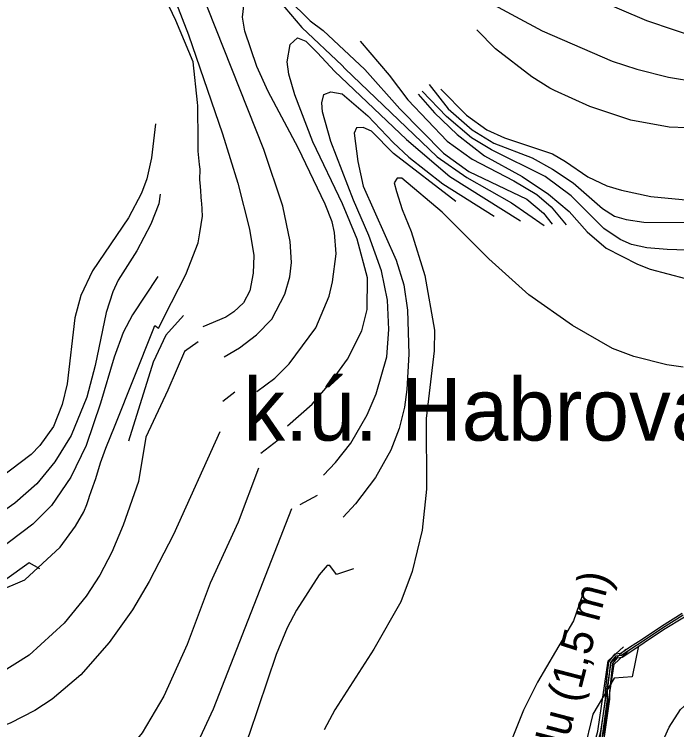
# Model space of a CAD drawing. Extents: x -1900516 to -575031, y -3809306 to -1157387.
# Drawn here: x -578473.4 to -578155.6, y -1158748.8 to -1158405.7 of the extents above; entities that cross this region are included whole.
import ezdxf

# ---------------------------------------------------------------- set-up
doc = ezdxf.new("R2010")
doc.units = 0
for name, color, linetype in [('01_SPRÁV_HRANICE', 7, 'Continuous'), ('01_VRSTEVNICE', 7, 'Continuous'), ('07_OCH_P A POPISY TI', 7, 'Continuous'), ('07_PLYNOVOD', 7, 'Continuous'), ('07_VODOVOD', 7, 'Continuous')]:
    doc.layers.add(name, color=color, linetype=linetype)

msp = doc.modelspace()

# ---------------------------------------------------------------- linework, layer by layer
at = {"layer": '01_SPRÁV_HRANICE'}
for p, q in [((-578395.81, -1158408.74), (-578400.47, -1158398.74)), ((-578395.81, -1158408.74), (-578400.47, -1158398.74)), ((-578387.52, -1158428.46), (-578395.81, -1158408.74)), ((-578387.52, -1158428.46), (-578395.81, -1158408.74)), ((-578385.48, -1158448), (-578387.52, -1158428.46)), ((-578385.48, -1158448), (-578387.52, -1158428.46)), ((-578385.3, -1158449.67), (-578385.48, -1158448)), ((-578385.3, -1158449.67), (-578385.48, -1158448)), ((-578385.27, -1158452.79), (-578385.3, -1158449.67)), ((-578385.27, -1158452.79), (-578385.3, -1158449.67)), ((-578385.17, -1158463.41), (-578385.27, -1158452.79)), ((-578385.17, -1158463.41), (-578385.27, -1158452.79)), ((-578385.09, -1158471.35), (-578385.17, -1158463.41)), ((-578385.09, -1158471.35), (-578385.17, -1158463.41)), ((-578384.48, -1158477.76), (-578385.09, -1158471.35)), ((-578384.48, -1158477.76), (-578385.09, -1158471.35)), ((-578384.27, -1158479.95), (-578384.48, -1158477.76)), ((-578384.27, -1158479.95), (-578384.48, -1158477.76)), ((-578384.3, -1158485.1), (-578384.27, -1158479.95)), ((-578384.3, -1158485.1), (-578384.27, -1158479.95)), ((-578384.08, -1158488.12), (-578384.3, -1158485.1)), ((-578384.08, -1158488.12), (-578384.3, -1158485.1)), ((-578383.52, -1158495.54), (-578384.08, -1158488.12)), ((-578383.52, -1158495.54), (-578384.08, -1158488.12)), ((-578383.48, -1158496.11), (-578383.52, -1158495.54)), ((-578383.48, -1158496.11), (-578383.52, -1158495.54)), ((-578383.11, -1158502.52), (-578383.48, -1158496.11)), ((-578383.11, -1158502.52), (-578383.48, -1158496.11)), ((-578384.39, -1158510.5), (-578383.11, -1158502.52)), ((-578384.39, -1158510.5), (-578383.11, -1158502.52)), ((-578385.18, -1158515.41), (-578384.39, -1158510.5)), ((-578385.18, -1158515.41), (-578384.39, -1158510.5)), ((-578391.1, -1158530.59), (-578385.18, -1158515.41)), ((-578391.1, -1158530.59), (-578385.18, -1158515.41)), ((-578397.98, -1158544.02), (-578391.1, -1158530.59)), ((-578397.98, -1158544.02), (-578391.1, -1158530.59)), ((-578404.22, -1158556.2), (-578397.98, -1158544.02)), ((-578404.22, -1158556.2), (-578397.98, -1158544.02)), ((-578406.73, -1158557.02), (-578405.95, -1158555.06)), ((-578406.73, -1158557.02), (-578405.95, -1158555.06)), ((-578405.95, -1158555.06), (-578404.22, -1158556.2)), ((-578405.95, -1158555.06), (-578404.22, -1158556.2)), ((-578424.95, -1158602.79), (-578406.73, -1158557.02)), ((-578424.95, -1158602.79), (-578406.73, -1158557.02)), ((-578429.47, -1158613.84), (-578424.95, -1158602.79)), ((-578429.47, -1158613.84), (-578424.95, -1158602.79)), ((-578432, -1158620.85), (-578429.47, -1158613.84)), ((-578432, -1158620.85), (-578429.47, -1158613.84)), ((-578434.23, -1158628.36), (-578432, -1158620.85)), ((-578434.23, -1158628.36), (-578432, -1158620.85)), ((-578436.33, -1158634.06), (-578434.23, -1158628.36)), ((-578436.33, -1158634.06), (-578434.23, -1158628.36)), ((-578437.44, -1158637.36), (-578436.33, -1158634.06)), ((-578437.44, -1158637.36), (-578436.33, -1158634.06)), ((-578438.63, -1158640.88), (-578437.48, -1158637.49)), ((-578438.63, -1158640.88), (-578437.48, -1158637.49)), ((-578437.48, -1158637.49), (-578437.44, -1158637.36)), ((-578437.48, -1158637.49), (-578437.44, -1158637.36)), ((-578439.98, -1158644.37), (-578438.63, -1158640.88)), ((-578439.98, -1158644.37), (-578438.63, -1158640.88)), ((-578444.04, -1158651.25), (-578439.98, -1158644.37)), ((-578444.04, -1158651.25), (-578439.98, -1158644.37)), ((-578451.4, -1158661.35), (-578444.04, -1158651.25)), ((-578451.4, -1158661.35), (-578444.04, -1158651.25)), ((-578468.26, -1158676.95), (-578451.4, -1158661.35)), ((-578468.26, -1158676.95), (-578451.4, -1158661.35)), ((-578482.31, -1158682.92), (-578468.26, -1158676.95)), ((-578482.31, -1158682.92), (-578468.26, -1158676.95))]:
    msp.add_line(p, q, dxfattribs=at)
at = {"layer": '01_VRSTEVNICE'}
for points in [[(-578348.74, -1158381.16), (-578359.04, -1158370.16), (-578383.03, -1158347.72), (-578410.12, -1158320.77), (-578418.02, -1158314.57), (-578423.95, -1158311.32), (-578426.2, -1158310.9), (-578430.15, -1158312.87), (-578430.58, -1158313.72), (-578429.73, -1158319.65), (-578423.24, -1158336.58), (-578413.93, -1158357.74), (-578407.16, -1158370.44), (-578389.8, -1158415.59), (-578373.44, -1158463), (-578366.1, -1158486.7), (-578360.6, -1158508.71), (-578358.48, -1158521.41), (-578358.76, -1158529.87), (-578360.45, -1158538.34), (-578363.42, -1158544.12), (-578368.07, -1158548.5), (-578371.88, -1158551.04), (-578382.89, -1158555.55)], [(-578039.61, -1158382.57), (-578046.81, -1158422.36), (-578051.04, -1158436.19), (-578056.96, -1158445.36), (-578060.63, -1158449.03), (-578065.29, -1158451.99), (-578072.06, -1158454.25), (-578080.53, -1158455.66), (-578108.46, -1158455.66), (-578123.98, -1158458.34), (-578142.33, -1158460.46), (-578159.26, -1158459.89), (-578177.6, -1158456.51), (-578197.35, -1158450.02), (-578214.28, -1158442.26), (-578216.54, -1158441.13), (-578225.15, -1158435.77), (-578242.5, -1158422.22), (-578251.53, -1158413.19)], [(-578372.73, -1158569.94), (-578365.39, -1158565.71), (-578357.21, -1158559.5), (-578349.87, -1158551.88), (-578343.66, -1158540.03), (-578341.12, -1158531.57), (-578340.42, -1158524.79), (-578340.98, -1158514.64), (-578344.51, -1158497.71), (-578353.68, -1158470.61), (-578384.44, -1158393.01)], [(-578073.33, -1158400.92), (-578083.63, -1158411.36), (-578090.4, -1158415.59), (-578096.05, -1158417.85), (-578108.46, -1158420.1), (-578125.39, -1158419.96), (-578143.45, -1158417.85), (-578169.91, -1158408.8), (-578208.18, -1158392.36)], [(-578342.25, -1158397.95), (-578331.39, -1158408.82), (-578325.18, -1158413.47), (-578305.15, -1158432.24), (-578288.5, -1158451.14), (-578267.47, -1158472.31), (-578255.34, -1158481.06), (-578227.55, -1158494.32), (-578219.5, -1158501.09), (-578215.41, -1158506.45)], [(-578357.07, -1158586.59), (-578348.32, -1158580.24), (-578341.55, -1158573.33), (-578328.71, -1158556.12), (-578322.36, -1158540.88), (-578320.67, -1158534.11), (-578318.97, -1158520.56), (-578319.82, -1158510.4), (-578320.95, -1158505.32), (-578324.19, -1158496.86), (-578337.17, -1158469.77), (-578351.57, -1158442.68), (-578357.07, -1158430.83), (-578362.85, -1158413.9), (-578363.84, -1158407.12), (-578363.14, -1158400.21)], [(-578346.34, -1158399.22), (-578335.48, -1158412.06), (-578316.15, -1158430.26), (-578314.88, -1158431.67), (-578270.58, -1158474.14), (-578256.33, -1158484.02), (-578234.88, -1158496.15), (-578219.22, -1158507.02)], [(-578247.86, -1158398.66), (-578220.21, -1158413.61), (-578186.63, -1158428.29), (-578174.78, -1158432.1), (-578159.54, -1158435.91), (-578145.99, -1158438.16), (-578129.06, -1158438.59), (-578080.81, -1158431.53), (-578073.47, -1158428.57), (-578067.55, -1158424.76), (-578060.77, -1158418.13), (-578056.68, -1158412.2), (-578053.16, -1158404.3)], [(-578342.25, -1158603.1), (-578330.54, -1158592.66), (-578321.94, -1158582.78), (-578313.47, -1158571.07), (-578306.7, -1158557.53), (-578304.02, -1158547.37), (-578303.88, -1158532.13), (-578308.96, -1158513.51), (-578315.87, -1158496.58), (-578330.12, -1158466.95), (-578338.73, -1158444.37), (-578341.69, -1158434.5), (-578342.4, -1158428.57), (-578340.99, -1158420.23), (-578337.59, -1158417.02), (-578333.58, -1158418.62), (-578327.86, -1158424.2), (-578319.82, -1158433.08), (-578285.25, -1158465.82), (-578264.37, -1158483.45), (-578230.51, -1158504.76)], [(-578307.4, -1158418.55), (-578293.58, -1158434.92), (-578284.55, -1158446.77), (-578265.64, -1158466.52), (-578253.79, -1158475.27), (-578233.75, -1158485.57), (-578222.75, -1158492.2), (-578215.83, -1158498.13), (-578208.63, -1158506.73)], [(-578109.31, -1158520.28), (-578160.1, -1158518.59), (-578169.98, -1158517.74), (-578177.32, -1158516.19), (-578182.68, -1158513.79), (-578190.58, -1158508.43), (-578206.24, -1158492.77), (-578218.66, -1158483.59), (-578244.48, -1158470.76), (-578254.07, -1158464.97), (-578266.06, -1158454.67), (-578277.77, -1158442.54)], [(-578274.39, -1158439.43), (-578265.22, -1158451.14), (-578253.79, -1158461.16), (-578243.35, -1158467.51), (-578225.01, -1158474.56), (-578215.13, -1158479.93), (-578205.25, -1158486.56), (-578191.14, -1158498.83), (-578185.5, -1158502.5), (-578179.86, -1158504.2), (-578171.39, -1158505.46), (-578137.81, -1158505.61)], [(-578268.74, -1158441.69), (-578256.47, -1158454.11), (-578246.73, -1158461.16), (-578238.27, -1158464.97), (-578215.13, -1158472.73), (-578208.92, -1158476.26), (-578198.2, -1158483.74), (-578189.17, -1158487.97), (-578182.11, -1158490.08), (-578168, -1158493.05), (-578149.66, -1158494.88)], [(-578325.04, -1158626.8), (-578319.26, -1158620.74), (-578311.92, -1158611.43), (-578304.16, -1158597.88), (-578299.79, -1158587.72), (-578294.7, -1158569.94), (-578293.72, -1158556.96), (-578294.28, -1158542.85), (-578297.24, -1158528.75), (-578303.31, -1158511.81), (-578310.65, -1158494.88), (-578321.51, -1158466.66), (-578325.46, -1158452.55), (-578325.89, -1158448.18), (-578324.9, -1158444.23), (-578321.51, -1158442.96), (-578316.15, -1158443.81), (-578303.73, -1158454.39), (-578291.6, -1158467.23), (-578284.1, -1158474.23), (-578267.76, -1158486.98), (-578243.21, -1158502.5)], [(-578279.61, -1158444.09), (-578271.85, -1158452.98), (-578260.98, -1158463.42), (-578247.86, -1158473.58), (-578229.8, -1158483.59), (-578217.1, -1158491.92), (-578207.23, -1158500.39), (-578198.48, -1158510.12), (-578189.45, -1158517.88), (-578174.35, -1158525.64), (-578168.29, -1158527.9), (-578151.35, -1158532.41), (-578139.5, -1158534.11), (-578127.09, -1158533.68), (-578117.63, -1158532.41)], [(-578405.6, -1158458.34), (-578407.58, -1158474.57), (-578409.84, -1158484.72), (-578412.38, -1158491.5), (-578418.58, -1158503.35), (-578435.8, -1158528.75), (-578441.44, -1158540.6), (-578444.41, -1158551.32), (-578447.93, -1158582.93), (-578450.47, -1158592.8), (-578454.56, -1158603.38), (-578461.2, -1158612.55), (-578465.29, -1158616.79), (-578503.81, -1158645.99)], [(-578261.55, -1158495.45), (-578291.46, -1158472.45), (-578302.04, -1158461.73), (-578305.99, -1158460.03), (-578309.14, -1158460.12), (-578310.37, -1158462.71), (-578308.53, -1158476.26), (-578305.99, -1158488.11), (-578290.19, -1158523.67), (-578286.52, -1158535.52), (-578284.69, -1158547.65), (-578284.12, -1158568.81), (-578285.11, -1158585.75), (-578286.24, -1158594.21), (-578288.78, -1158604.37), (-578292.73, -1158614.81), (-578300.07, -1158627.93), (-578309.66, -1158640.49), (-578315.59, -1158646.84)], [(-578152.48, -1158575.02), (-578160.39, -1158573.89), (-578176.19, -1158569.8), (-578186.35, -1158565.99), (-578205.54, -1158554.99), (-578226.56, -1158540.31), (-578245.75, -1158522.96), (-578268.04, -1158500.67), (-578287.51, -1158484.3), (-578289.63, -1158484.3), (-578291.08, -1158486.64), (-578290.05, -1158490.79), (-578287.37, -1158499.4), (-578282.99, -1158509.84), (-578276.36, -1158531), (-578271.85, -1158557.25), (-578271.99, -1158567.12), (-578275.8, -1158599.57), (-578275.66, -1158633.44), (-578277.77, -1158653.19), (-578282.57, -1158672.94), (-578287.93, -1158687.47), (-578300.91, -1158710.19), (-578319.54, -1158739.26), (-578324.76, -1158748.99)], [(-578403.35, -1158491.92), (-578404.05, -1158496.58), (-578407.86, -1158506.45), (-578414.63, -1158519.15), (-578423.52, -1158533.26), (-578426.06, -1158538.9), (-578429.31, -1158548.78), (-578434.53, -1158574.18), (-578438.62, -1158589.42), (-578446.1, -1158607.76), (-578453.86, -1158620.31), (-578462.61, -1158630.9), (-578473.19, -1158640.21), (-578487.86, -1158650.37)], [(-578404.48, -1158531.43), (-578416.61, -1158549.91), (-578421.12, -1158558.38), (-578425.5, -1158570.23), (-578431.99, -1158592.24), (-578438.9, -1158612.55), (-578446.24, -1158627.79), (-578455.55, -1158641.34), (-578464.44, -1158650.23), (-578487.02, -1158667.16)], [(-578392.18, -1158550.19), (-578400.67, -1158559.64), (-578406.73, -1158572.62), (-578418.58, -1158610.44)], [(-578385.15, -1158562.89), (-578391.78, -1158567.41), (-578399.68, -1158586.03), (-578410.24, -1158608.58), (-578413.79, -1158629.77), (-578421.12, -1158650.79), (-578426.63, -1158663.77), (-578432.41, -1158674.78), (-578438.9, -1158684.79), (-578449.48, -1158697.77), (-578466.27, -1158713.15), (-578479.96, -1158721.76)], [(-578367.51, -1158587.02), (-578373.29, -1158591.39)], [(-578374.85, -1158605.92), (-578397, -1158655.16), (-578408.71, -1158677.74), (-578416.61, -1158691.28), (-578427.9, -1158707.09), (-578441.44, -1158722.47), (-578455.13, -1158734.18), (-578463.45, -1158739.68), (-578475.3, -1158745.75), (-578490.26, -1158751.11), (-578497.75, -1158751.97), (-578504.37, -1158751.11), (-578517.07, -1158752.94), (-578529.62, -1158758.73), (-578547.83, -1158771), (-578563.35, -1158779.61), (-578576.89, -1158786.1), (-578589.59, -1158790.05), (-578609.91, -1158793.58), (-578626.56, -1158793.29), (-578663.24, -1158789.91), (-578679.04, -1158790.47), (-578693.86, -1158792.59)], [(-578346.77, -1158610.01), (-578355.09, -1158616.36)], [(-578356.22, -1158623.42), (-578365.96, -1158649.24), (-578379.36, -1158678.59), (-578390.37, -1158707.93), (-578401.65, -1158732.77), (-578412.09, -1158750.4), (-578420, -1158760.14), (-578428.74, -1158768.88), (-578439.75, -1158777.49), (-578453.01, -1158784.12), (-578460.63, -1158785.96), (-578468.25, -1158786.66), (-578479.26, -1158785.53)], [(-578328.14, -1158636.54), (-578336.44, -1158641.05)], [(-578340.42, -1158642.89), (-578377.95, -1158738.97), (-578387.4, -1158759.29), (-578398.69, -1158779.33), (-578407.02, -1158791.04), (-578415.48, -1158799.93), (-578424.79, -1158806.84), (-578433.82, -1158811.21), (-578445.39, -1158814.6), (-578456.4, -1158815.16), (-578466.56, -1158813.75), (-578471.64, -1158812.34), (-578493.65, -1158802.89)], [(-578461.14, -1158671.68), (-578466.27, -1158668.85), (-578478.13, -1158677.31), (-578494.35, -1158687.61), (-578521.44, -1158702.01), (-578539.5, -1158712.73), (-578544.86, -1158717.1)], [(-578310.65, -1158671.67), (-578318.83, -1158674.49), (-578321.94, -1158670.12), (-578323.21, -1158670.12), (-578327.16, -1158674.64), (-578338.02, -1158691.57), (-578342.4, -1158700.03), (-578347.76, -1158712.73), (-578360.74, -1158751.11), (-578371.88, -1158779.61), (-578382.04, -1158803.31), (-578397.6, -1158830.43)], [(-578201.02, -1158684.65), (-578205.11, -1158696.65), (-578222.33, -1158725.99), (-578229.1, -1158739.54), (-578234.6, -1158753.08), (-578240.24, -1158773.4), (-578242.22, -1158793.72), (-578243.63, -1158834.35), (-578246.59, -1158859.18), (-578249.13, -1158872.73), (-578260.28, -1158915.62), (-578269.33, -1158955.21), (-578271.41, -1158960.82)], [(-578173.86, -1158708.68), (-578177.03, -1158723.45), (-578185.64, -1158724.16), (-578195.85, -1158741.35), (-578200.17, -1158759.29), (-578189.73, -1158769.59), (-578193.12, -1158781.02), (-578207.79, -1158824.48), (-578215.13, -1158852.41), (-578222.89, -1158886.27), (-578224.58, -1158890.51), (-578228.53, -1158894.03)], [(-578164.48, -1158759.29), (-578159.26, -1158747.58), (-578153.75, -1158739.11), (-578141.76, -1158728.53), (-578132.73, -1158725.15), (-578124.83, -1158724.86), (-578116.93, -1158726.56), (-578098.73, -1158736.15), (-578091.53, -1158739.96), (-578067.83, -1158755.76)], [(-578164.48, -1158759.29), (-578159.26, -1158747.58), (-578153.75, -1158739.11), (-578141.76, -1158728.53), (-578132.73, -1158725.15), (-578124.83, -1158724.86), (-578116.93, -1158726.56), (-578098.73, -1158736.15), (-578091.53, -1158739.96), (-578067.83, -1158755.76)]]:
    msp.add_lwpolyline(points, dxfattribs=at)
at = {"layer": '07_OCH_P A POPISY TI'}
for points in [[(-578192.31, -1158752.79), (-578189.73, -1158734.12), (-578189.74, -1158730.38), (-578188.18, -1158716.25), (-578185.12, -1158712.41), (-578182.44, -1158712.11), (-578178.18, -1158709.3), (-578172.23, -1158705.35), (-578162.94, -1158699.19), (-578152.99, -1158692.98)], [(-578190.35, -1158753.21), (-578187.73, -1158734.26), (-578187.74, -1158730.48), (-578186.26, -1158717.05), (-578184.08, -1158714.31), (-578181.74, -1158714.05), (-578177.08, -1158710.96), (-578171.13, -1158707.01), (-578161.86, -1158700.87), (-578151.93, -1158694.68)], [(-578249.69, -1158933.16), (-578201.17, -1158777.44), (-578193.43, -1158749.48), (-578188.4, -1158715.87), (-578181.06, -1158709.09)], [(-578246.82, -1158934.05), (-578198.29, -1158778.28), (-578190.49, -1158750.1), (-578185.59, -1158717.35), (-578179.02, -1158711.29)]]:
    msp.add_lwpolyline(points, dxfattribs=at)
at = {"layer": '07_PLYNOVOD'}
msp.add_lwpolyline([(-578191.33, -1158753), (-578188.73, -1158734.19), (-578188.74, -1158730.43), (-578187.22, -1158716.65), (-578184.6, -1158713.36), (-578182.09, -1158713.08), (-578177.63, -1158710.13), (-578171.68, -1158706.18), (-578162.4, -1158700.03), (-578152.46, -1158693.83)], dxfattribs=at)
at = {"layer": '07_VODOVOD'}
msp.add_lwpolyline([(-578248.26, -1158933.61), (-578199.73, -1158777.86), (-578191.96, -1158749.79), (-578186.99, -1158716.61), (-578180.04, -1158710.19)], dxfattribs=at)

# ---------------------------------------------------------------- texts
at = {"layer": '01_SPRÁV_HRANICE'}
msp.add_text('k.ú. Habrovany', height=30, dxfattribs=at).set_placement((-578363.53, -1158610.19))
at = {"layer": '07_OCH_P A POPISY TI'}
msp.add_text('OP vodovodu (1,5 m)', height=15, rotation=75.4416, dxfattribs=at).set_placement((-578235.1, -1158859.47))

doc.saveas('drawing.dxf')
